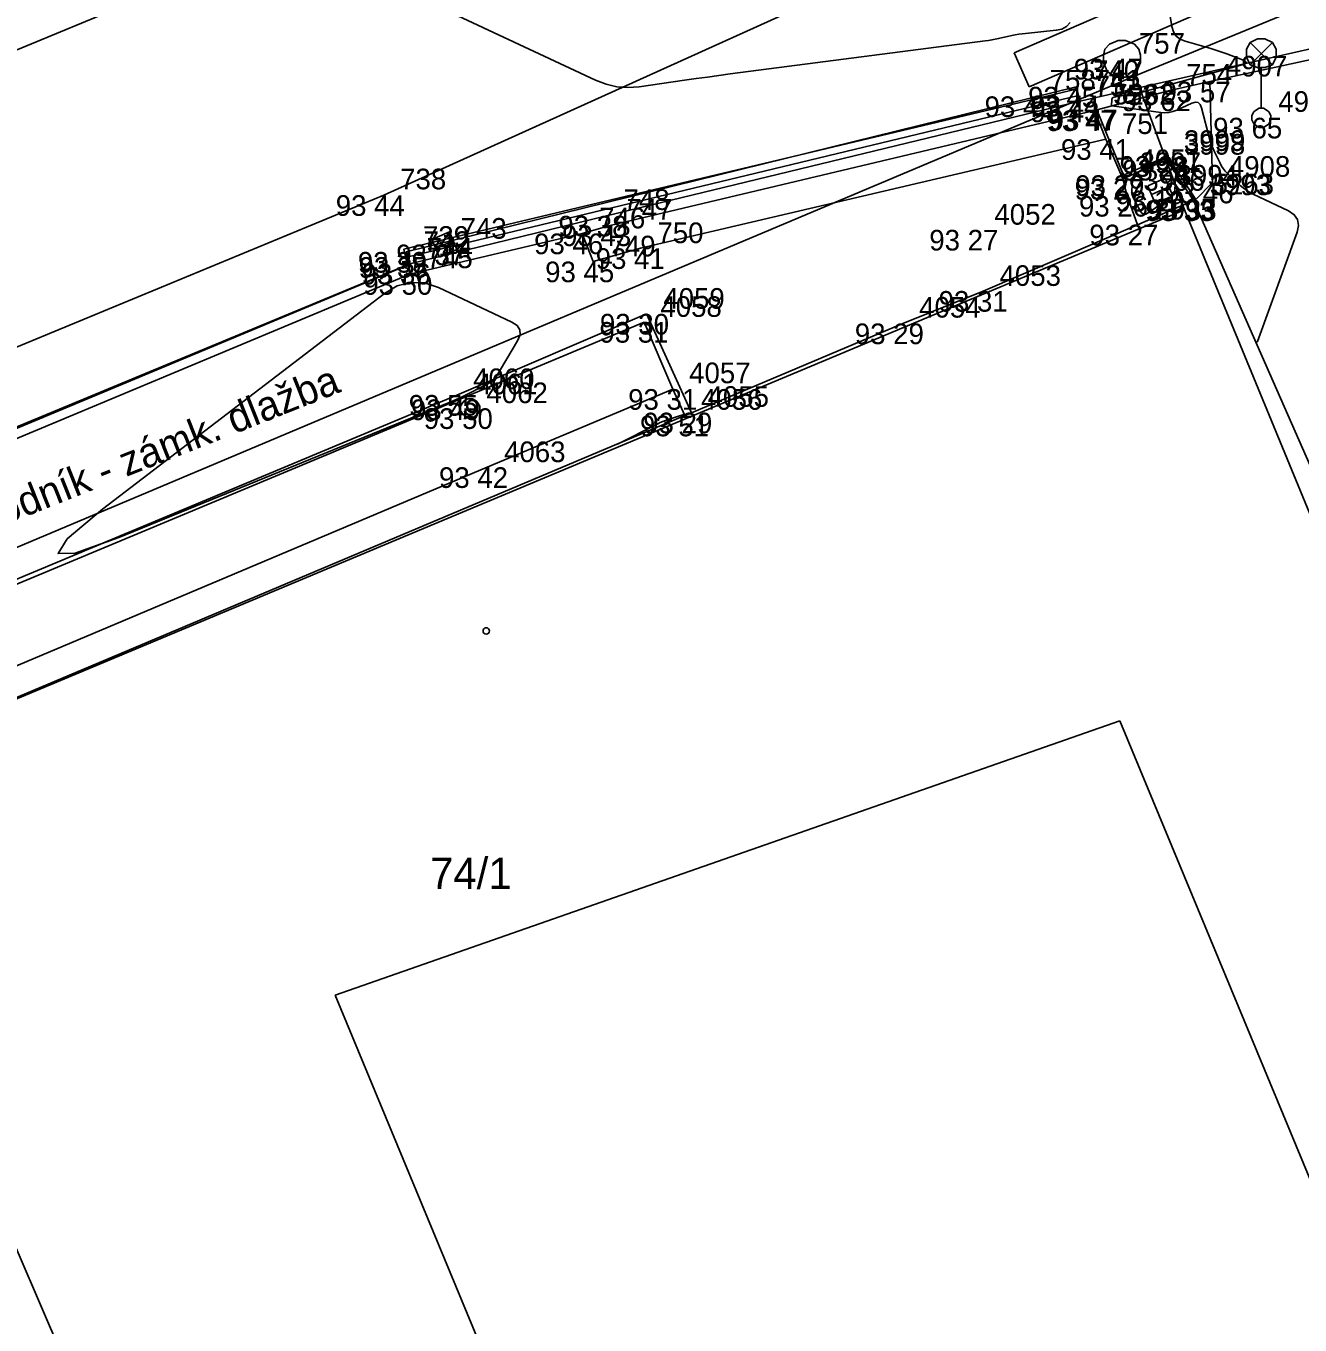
# Model space of a CAD drawing. Extents: x -711081 to -709338, y -1025122 to -1024092.
# Drawn here: x -709841.94 to -709824.66, y -1024568.73 to -1024551.11 of the extents above; entities that cross this region are included whole.
import ezdxf

# ---------------------------------------------------------------- set-up
doc = ezdxf.new("R2010")
doc.units = 0
for name, color, linetype in [('Ex_Minor Contours', 7, 'Continuous'), ('Z_body', 7, 'Continuous'), ('Z_body_cisla', 7, 'Continuous'), ('Z_body_vysky_redukovane', 7, 'Continuous'), ('Z_budova', 7, 'Continuous'), ('Z_chodnik', 7, 'Continuous'), ('Z_hrany_paty', 7, 'Continuous'), ('Z_katastr_cisla_stavebni', 7, 'Continuous'), ('Z_katastr_hranice', 7, 'Continuous'), ('Z_katastr_vnitrni_kresba', 7, 'Continuous'), ('Z_katastr_znacky_budov', 7, 'Continuous'), ('Z_komunikace', 7, 'Continuous'), ('Z_komunikace_osa', 7, 'Continuous'), ('Z_obruba', 7, 'Continuous'), ('Z_popisy', 7, 'Continuous'), ('Z_rozhranni', 7, 'Continuous'), ('Z_site_kanalizace_znaky', 7, 'Continuous'), ('Z_site_vo_znaky', 7, 'Continuous'), ('Z_site_vodovod_znaky', 7, 'Continuous'), ('Z_vdz25_plna', 7, 'Continuous'), ('Z_vdz_prechod', 7, 'Continuous'), ('Z_vstupy', 7, 'Continuous'), ('Z_zlabek', 7, 'Continuous')]:
    doc.layers.add(name, color=color, linetype=linetype)

# ---------------------------------------------------------------- blocks, each defined once
blk = doc.blocks.new('POINT_DISPLAY')
blk.add_line((0, 0), (0, 0))
blk = doc.blocks.new('Z614')
for p, q in [((-0.13, 0.03), (-0.1, 0.08)), ((-0.13, -0.03), (-0.13, 0.03)), ((-0.1, 0.08), (-0.08, 0.1)), ((-0.08, 0.1), (-0.03, 0.13)), ((-0.03, 0.13), (0.03, 0.13)), ((0.03, 0.13), (0.08, 0.1)), ((0.08, 0.1), (0.1, 0.08)), ((0.1, 0.08), (0.13, 0.03)), ((0.13, 0.03), (0.13, -0.03)), ((-0.1, -0.08), (-0.13, -0.03)), ((-0.08, -0.1), (-0.1, -0.08)), ((-0.03, -0.13), (-0.08, -0.1)), ((0.03, -0.13), (-0.03, -0.13)), ((0.08, -0.1), (0.03, -0.13)), ((0.1, -0.08), (0.08, -0.1)), ((0.13, -0.03), (0.1, -0.08))]:
    blk.add_line(p, q)
blk = doc.blocks.new('Z34')
for p, q in [((-0.15, 1.02), (-0.05, 1.07)), ((-0.05, 1.07), (0.05, 1.07)), ((0.05, 1.07), (0.15, 1.02)), ((-0.2, 0.93), (-0.15, 1.02)), ((-0.2, 0.82), (-0.2, 0.93)), ((0.15, 0.72), (-0.15, 1.02)), ((0.15, 1.02), (-0.15, 0.72)), ((0.15, 1.02), (0.2, 0.93)), ((0.2, 0.93), (0.2, 0.82)), ((-0.15, 0.72), (-0.2, 0.82)), ((-0.05, 0.68), (-0.15, 0.72)), ((0.15, 0.72), (0.05, 0.68)), ((0.2, 0.82), (0.15, 0.72)), ((0.05, 0.68), (-0.05, 0.68)), ((0, 0.13), (0, 0.68)), ((-0.13, 0.03), (-0.1, 0.08)), ((-0.13, -0.03), (-0.13, 0.03)), ((-0.1, 0.08), (-0.08, 0.1)), ((-0.08, 0.1), (-0.03, 0.13)), ((-0.03, 0.13), (0.03, 0.13)), ((0.03, 0.13), (0.08, 0.1)), ((0.08, 0.1), (0.1, 0.08)), ((0.1, 0.08), (0.13, 0.03)), ((0.13, 0.03), (0.13, -0.03)), ((-0.1, -0.08), (-0.13, -0.03)), ((-0.08, -0.1), (-0.1, -0.08)), ((-0.03, -0.13), (-0.08, -0.1)), ((0.03, -0.13), (-0.03, -0.13)), ((0.08, -0.1), (0.03, -0.13)), ((0.1, -0.08), (0.08, -0.1)), ((0.13, -0.03), (0.1, -0.08))]:
    blk.add_line(p, q)
blk = doc.blocks.new('Z620')
for p, q in [((-0.23, 0.13), (-0.17, 0.2)), ((-0.17, 0.2), (-0.05, 0.25)), ((-0.05, 0.25), (0.05, 0.25)), ((0.05, 0.25), (0.17, 0.2)), ((0.17, 0.2), (0.23, 0.13)), ((-0.25, 0.05), (-0.23, 0.13)), ((-0.25, -0.05), (-0.25, 0.05)), ((0.23, 0.13), (0.25, 0.05)), ((0.25, 0.05), (0.25, -0.05)), ((-0.2, -0.17), (-0.25, -0.05)), ((-0.13, -0.23), (-0.2, -0.17)), ((0.2, -0.17), (0.13, -0.23)), ((0.25, -0.05), (0.2, -0.17)), ((-0.05, -0.25), (-0.13, -0.23)), ((0.05, -0.25), (-0.05, -0.25)), ((0.13, -0.23), (0.05, -0.25))]:
    blk.add_line(p, q)
blk = doc.blocks.new('Z46260')
for p, q in [((0.13, 0.13), (-0.13, 0.13)), ((-0.13, 0.13), (-0.13, -0.13)), ((0.13, 0), (-0.13, 0)), ((0.13, -0.13), (0.13, 0.13)), ((-0.13, -0.13), (0.13, -0.13))]:
    blk.add_line(p, q)

msp = doc.modelspace()

# ---------------------------------------------------------------- linework, layer by layer
at = {"layer": 'Ex_Minor Contours'}
for points in [[(-709826.732, -1024549.131), (-709826.402, -1024551.122), (-709826.381, -1024551.194), (-709826.345, -1024551.251), (-709826.292, -1024551.294), (-709826.223, -1024551.323), (-709825.873, -1024551.422), (-709825.819, -1024551.438), (-709825.765, -1024551.455), (-709825.712, -1024551.473), (-709825.658, -1024551.493), (-709825.447, -1024551.572), (-709825.407, -1024551.591), (-709825.395, -1024551.609), (-709825.409, -1024551.626), (-709825.45, -1024551.642), (-709826.674, -1024551.976), (-709826.727, -1024551.99), (-709826.781, -1024552.003), (-709826.834, -1024552.014), (-709826.888, -1024552.025), (-709827.185, -1024552.08), (-709827.198, -1024552.084), (-709827.207, -1024552.091), (-709827.213, -1024552.1), (-709827.215, -1024552.113), (-709827.222, -1024552.197), (-709827.219, -1024552.199), (-709826.553, -1024552.289), (-709826.498, -1024552.293), (-709826.443, -1024552.288), (-709826.39, -1024552.276), (-709826.337, -1024552.257), (-709826.131, -1024552.161), (-709826.084, -1024552.147), (-709826.046, -1024552.153), (-709826.018, -1024552.179), (-709825.999, -1024552.224), (-709825.886, -1024552.657), (-709825.874, -1024552.699), (-709825.86, -1024552.74), (-709825.844, -1024552.781), (-709825.826, -1024552.82), (-709825.749, -1024552.977), (-709825.729, -1024553.014), (-709825.705, -1024553.05), (-709825.678, -1024553.083), (-709825.648, -1024553.114), (-709825.475, -1024553.277), (-709825.434, -1024553.312), (-709825.391, -1024553.344), (-709825.346, -1024553.372), (-709825.298, -1024553.397), (-709824.822, -1024553.623), (-709824.743, -1024553.675), (-709824.697, -1024553.74), (-709824.684, -1024553.82), (-709824.703, -1024553.912), (-709825.242, -1024555.394), (-709825.243, -1024555.396), (-709825.245, -1024555.398), (-709825.247, -1024555.4), (-709825.249, -1024555.401), (-709825.263, -1024555.406)], [(-709836.368, -1024550.848), (-709834.218, -1024551.851), (-709834.075, -1024551.906), (-709833.929, -1024551.939), (-709833.78, -1024551.95), (-709833.627, -1024551.939), (-709833.011, -1024551.85), (-709832.857, -1024551.829), (-709832.702, -1024551.807), (-709832.548, -1024551.786), (-709832.394, -1024551.766), (-709828.936, -1024551.317), (-709828.89, -1024551.31), (-709828.844, -1024551.303), (-709828.799, -1024551.294), (-709828.753, -1024551.285), (-709828.572, -1024551.245), (-709828.526, -1024551.235), (-709828.48, -1024551.227), (-709828.434, -1024551.221), (-709828.388, -1024551.215), (-709827.972, -1024551.173), (-709827.895, -1024551.156), (-709827.831, -1024551.12), (-709827.782, -1024551.067)], [(-709833.924, -1024556.785), (-709833.376, -1024556.512), (-709833.342, -1024556.495), (-709833.307, -1024556.48), (-709833.271, -1024556.466), (-709833.235, -1024556.454), (-709833.023, -1024556.384), (-709833.021, -1024556.383), (-709833.018, -1024556.383), (-709833.017, -1024556.384), (-709833.015, -1024556.386), (-709833.006, -1024556.398)]]:
    msp.add_lwpolyline(points, dxfattribs=at)
for points in [[(-709826.932, -1024553.214), (-709826.938, -1024553.231), (-709826.942, -1024553.249), (-709826.943, -1024553.266), (-709826.945, -1024553.365), (-709826.944, -1024553.387), (-709826.94, -1024553.409), (-709826.934, -1024553.429), (-709826.924, -1024553.45), (-709826.831, -1024553.624), (-709826.81, -1024553.652), (-709826.785, -1024553.666), (-709826.757, -1024553.665), (-709826.726, -1024553.65), (-709826.428, -1024553.447), (-709826.401, -1024553.424), (-709826.381, -1024553.398), (-709826.369, -1024553.367), (-709826.363, -1024553.333), (-709826.35, -1024553.116), (-709826.349, -1024553.114), (-709826.348, -1024553.113), (-709826.341, -1024553.11), (-709826.341, -1024553.109), (-709826.341, -1024553.108), (-709826.433, -1024552.954), (-709826.45, -1024552.932), (-709826.47, -1024552.921), (-709826.494, -1024552.919), (-709826.52, -1024552.926), (-709826.736, -1024553.022), (-709826.751, -1024553.029), (-709826.764, -1024553.036), (-709826.778, -1024553.044), (-709826.791, -1024553.052), (-709826.844, -1024553.086), (-709826.856, -1024553.095), (-709826.867, -1024553.106), (-709826.877, -1024553.118), (-709826.886, -1024553.131), (-709826.924, -1024553.198)], [(-709835.283, -1024555.178), (-709835.246, -1024555.237), (-709835.244, -1024555.306), (-709835.278, -1024555.386), (-709835.583, -1024555.896), (-709835.584, -1024555.898), (-709835.584, -1024555.9), (-709835.584, -1024555.902), (-709835.582, -1024555.903), (-709835.575, -1024555.91), (-709835.573, -1024555.912), (-709835.573, -1024555.913), (-709835.574, -1024555.915), (-709835.575, -1024555.916), (-709835.949, -1024556.106), (-709836.012, -1024556.137), (-709836.076, -1024556.167), (-709836.141, -1024556.196), (-709836.206, -1024556.223), (-709840.686, -1024558.052), (-709841.276, -1024558.263), (-709841.509, -1024558.27), (-709841.385, -1024558.072), (-709840.905, -1024557.67), (-709837.083, -1024554.743), (-709836.909, -1024554.639), (-709836.728, -1024554.592), (-709836.541, -1024554.6), (-709836.349, -1024554.664), (-709835.356, -1024555.13)]]:
    msp.add_lwpolyline(points, close=True, dxfattribs=at)
at = {"layer": 'Z_budova'}
for p, q in [((-709826.11, -1024553.48), (-709826.87, -1024553.81)), ((-709826.11, -1024553.48), (-709823.67, -1024559.03)), ((-709828.96, -1024554.71), (-709830.05, -1024555.15)), ((-709833.01, -1024556.4), (-709844.89, -1024561.41)), ((-709832.92, -1024556.36), (-709833.01, -1024556.4))]:
    msp.add_line(p, q, dxfattribs=at)
at = {"layer": 'Z_chodnik'}
for p, q in [((-709827.45, -1024552.26), (-709827.3, -1024552.65)), ((-709827.3, -1024552.65), (-709827.07, -1024553.19)), ((-709827.01, -1024553.42), (-709827.07, -1024553.19)), ((-709827.01, -1024553.42), (-709826.87, -1024553.81)), ((-709833.53, -1024555.02), (-709836.1, -1024556.12)), ((-709833.53, -1024555.02), (-709832.92, -1024556.36)), ((-709836.1, -1024556.12), (-709849.57, -1024561.75))]:
    msp.add_line(p, q, dxfattribs=at)
at = {"layer": 'Z_hrany_paty'}
for p in [(-709825.89, -1024551.87), (-709826.08, -1024553.47)]:
    msp.add_line(p, (-709825.85, -1024553.24), dxfattribs=at)
at = {"layer": 'Z_katastr_hranice'}
for p, q in [((-709808.2, -1024544.08), (-709826.9, -1024551.79)), ((-709826.9, -1024551.79), (-709827.66, -1024552.11)), ((-709826.23, -1024553.61), (-709826.9, -1024551.79)), ((-709827.66, -1024552.11), (-709845.54, -1024559.65)), ((-709836.82, -1024554.14), (-709827.7, -1024551.97)), ((-709827.7, -1024551.97), (-709827.66, -1024552.11)), ((-709823.95, -1024559.15), (-709826.23, -1024553.61)), ((-709836.77, -1024554.36), (-709836.82, -1024554.14)), ((-709850.71, -1024560.17), (-709836.77, -1024554.36)), ((-709844.8, -1024561.38), (-709839.9, -1024572.74))]:
    msp.add_line(p, q, dxfattribs=at)
at = {"layer": 'Z_katastr_vnitrni_kresba'}
for p, q in [((-709826.23, -1024553.61), (-709844.8, -1024561.38)), ((-709837.75, -1024564.26), (-709827.11, -1024560.54)), ((-709822.5, -1024571.65), (-709827.11, -1024560.54)), ((-709835.08, -1024570.7), (-709837.75, -1024564.26))]:
    msp.add_line(p, q, dxfattribs=at)
at = {"layer": 'Z_katastr_znacky_budov'}
msp.add_circle((-709835.702, -1024559.32), 0.0437, dxfattribs=at)
at = {"layer": 'Z_komunikace'}
for p, q in [((-709827.67, -1024552.14), (-709824.01, -1024551.31)), ((-709834.07, -1024553.69), (-709827.67, -1024552.14)), ((-709836.74, -1024554.34), (-709834.07, -1024553.69)), ((-709851.14, -1024560.31), (-709836.74, -1024554.34))]:
    msp.add_line(p, q, dxfattribs=at)
at = {"layer": 'Z_komunikace_osa'}
msp.add_line((-709852.88, -1024555.91), (-709836.73, -1024549.23), dxfattribs=at)
at = {"layer": 'Z_obruba'}
for p, q in [((-709825.89, -1024551.87), (-709823.93, -1024551.44)), ((-709826.43, -1024551.99), (-709825.89, -1024551.87)), ((-709827.45, -1024552.26), (-709826.43, -1024551.99)), ((-709834.02, -1024553.82), (-709827.45, -1024552.26)), ((-709827.06, -1024553.14), (-709827.42, -1024552.25)), ((-709826.46, -1024552.88), (-709827.06, -1024553.14)), ((-709826.46, -1024552.88), (-709826.08, -1024553.47)), ((-709826.11, -1024553.48), (-709826.08, -1024553.47)), ((-709834.4, -1024553.93), (-709834.02, -1024553.82)), ((-709836.74, -1024554.48), (-709834.4, -1024553.93)), ((-709851.1, -1024560.48), (-709836.74, -1024554.48)), ((-709833.56, -1024555.13), (-709836.07, -1024556.18)), ((-709833.17, -1024556.04), (-709833.56, -1024555.13)), ((-709833.17, -1024556.04), (-709833.01, -1024556.4)), ((-709836.07, -1024556.18), (-709849.57, -1024561.82))]:
    msp.add_line(p, q, dxfattribs=at)
at = {"layer": 'Z_rozhranni'}
for p, q in [((-709836.79, -1024554.18), (-709827.7, -1024551.94)), ((-709827.7, -1024551.94), (-709827.67, -1024552.06)), ((-709827.67, -1024552.06), (-709827.67, -1024552.14)), ((-709833.61, -1024554.13), (-709827.3, -1024552.65)), ((-709827.07, -1024553.19), (-709826.47, -1024552.93)), ((-709826.47, -1024552.93), (-709826.11, -1024553.48)), ((-709834.25, -1024554.31), (-709834.4, -1024553.93)), ((-709836.79, -1024554.18), (-709836.78, -1024554.25)), ((-709834.25, -1024554.31), (-709833.61, -1024554.13)), ((-709836.78, -1024554.25), (-709836.74, -1024554.34)), ((-709835.69, -1024557.1), (-709833.17, -1024556.04)), ((-709835.69, -1024557.1), (-709845.01, -1024561.03))]:
    msp.add_line(p, q, dxfattribs=at)
at = {"layer": 'Z_vdz25_plna'}
for p, q in [((-709837.09, -1024553.41), (-709829.73, -1024550.08)), ((-709851.52, -1024559.37), (-709837.09, -1024553.41))]:
    msp.add_line(p, q, dxfattribs=at)
at = {"layer": 'Z_vdz_prechod'}
for p, q in [((-709824.79, -1024549.85), (-709828.54, -1024551.48)), ((-709828.34, -1024551.94), (-709824.59, -1024550.31)), ((-709828.54, -1024551.48), (-709828.34, -1024551.94))]:
    msp.add_line(p, q, dxfattribs=at)
at = {"layer": 'Z_vstupy'}
for p, q in [((-709828.96, -1024554.71), (-709826.87, -1024553.81)), ((-709832.92, -1024556.36), (-709830.05, -1024555.15))]:
    msp.add_line(p, q, dxfattribs=at)
at = {"layer": 'Z_zlabek'}
msp.add_line((-709827.67, -1024552.06), (-709836.78, -1024554.25), dxfattribs=at)

# ---------------------------------------------------------------- block references
at = {"layer": 'Z_body'}
for p in [(-709827.08, -1024551.56), (-709827.7, -1024551.94), (-709825.89, -1024551.87), (-709828.29, -1024552.07), (-709827.67, -1024552.06), (-709826.43, -1024551.99), (-709827.67, -1024552.14), (-709827.45, -1024552.26), (-709827.42, -1024552.25), (-709825.19, -1024552.36), (-709827.3, -1024552.65), (-709826.47, -1024552.93), (-709826.46, -1024552.88), (-709827.06, -1024553.14), (-709827.07, -1024553.19), (-709826.56, -1024553.35), (-709825.85, -1024553.24), (-709837.09, -1024553.41), (-709827.01, -1024553.42), (-709826.11, -1024553.48), (-709826.08, -1024553.47), (-709834.07, -1024553.69), (-709834.02, -1024553.82), (-709829.04, -1024553.88), (-709826.87, -1024553.81), (-709834.4, -1024553.93), (-709836.79, -1024554.18), (-709836.27, -1024554.08), (-709833.61, -1024554.13), (-709836.78, -1024554.25), (-709836.74, -1024554.34), (-709834.25, -1024554.31), (-709836.74, -1024554.48), (-709828.96, -1024554.71), (-709833.53, -1024555.02), (-709833.56, -1024555.13), (-709830.05, -1024555.15), (-709836.1, -1024556.12), (-709833.17, -1024556.04), (-709836.07, -1024556.18), (-709835.92, -1024556.3), (-709833.01, -1024556.4), (-709832.92, -1024556.36), (-709835.69, -1024557.1)]:
    msp.add_blockref('POINT_DISPLAY', p, dxfattribs=at)
at = {"layer": 'Z_site_kanalizace_znaky'}
msp.add_blockref('Z620', (-709827.08, -1024551.56), dxfattribs=at)
at = {"layer": 'Z_site_kanalizace_znaky', "rotation": 23.399999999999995}
for p in [(-709826.56, -1024553.35), (-709836.27, -1024554.08)]:
    msp.add_blockref('Z46260', p, dxfattribs=at)
at = {"layer": 'Z_site_vo_znaky'}
msp.add_blockref('Z34', (-709825.19, -1024552.36), dxfattribs=at)
at = {"layer": 'Z_site_vodovod_znaky'}
msp.add_blockref('Z614', (-709835.92, -1024556.3), dxfattribs=at)

# ---------------------------------------------------------------- texts
at = {"layer": 'Z_body_cisla'}
for s, p in [('757', (-709826.85, -1024551.49)), ('740', (-709827.47, -1024551.86)), ('4907', (-709825.67, -1024551.8)), ('758', (-709828.06, -1024551.99)), ('741', (-709827.45, -1024551.99)), ('754', (-709826.21, -1024551.91)), ('752', (-709827.45, -1024552.07)), ('753', (-709827.22, -1024552.19)), ('5262', (-709827.2, -1024552.18)), ('4906', (-709824.96, -1024552.28)), ('751', (-709827.08, -1024552.58)), ('3999', (-709826.24, -1024552.81)), ('3998', (-709826.24, -1024552.86)), ('4051', (-709826.84, -1024553.07)), ('3997', (-709826.84, -1024553.11)), ('3994', (-709826.34, -1024553.28)), ('4908', (-709825.63, -1024553.16)), ('738', (-709836.87, -1024553.33)), ('3996', (-709826.79, -1024553.35)), ('3993', (-709825.89, -1024553.41)), ('5263', (-709825.85, -1024553.4)), ('748', (-709833.84, -1024553.61)), ('747', (-709833.8, -1024553.74)), ('4052', (-709828.81, -1024553.81)), ('3995', (-709826.64, -1024553.74)), ('746', (-709834.17, -1024553.86)), ('739', (-709836.56, -1024554.11)), ('743', (-709836.05, -1024554)), ('750', (-709833.38, -1024554.06)), ('742', (-709836.55, -1024554.18)), ('744', (-709836.51, -1024554.27)), ('749', (-709834.03, -1024554.24)), ('745', (-709836.51, -1024554.4)), ('4053', (-709828.74, -1024554.64)), ('4059', (-709833.3, -1024554.95)), ('4058', (-709833.34, -1024555.06)), ('4054', (-709829.83, -1024555.07)), ('4060', (-709835.88, -1024556.04)), ('4057', (-709832.95, -1024555.96)), ('4061', (-709835.84, -1024556.11)), ('4062', (-709835.7, -1024556.23)), ('4055', (-709832.7, -1024556.28)), ('4056', (-709832.79, -1024556.32)), ('4063', (-709835.46, -1024557.03))]:
    msp.add_text(s, height=0.28, dxfattribs=at).set_placement(p)
at = {"layer": 'Z_body_vysky_redukovane'}
for s, p in [('93 47', (-709827.733, -1024551.84)), ('93 45', (-709828.353, -1024552.22)), ('93 57', (-709826.543, -1024552.15)), ('93 45', (-709828.943, -1024552.35)), ('93 44', (-709828.323, -1024552.34)), ('93 62', (-709827.083, -1024552.27)), ('93 43', (-709828.323, -1024552.42)), ('93 47', (-709828.103, -1024552.54)), ('93 47', (-709828.073, -1024552.53)), ('93 65', (-709825.843, -1024552.64)), ('93 41', (-709827.907, -1024552.93)), ('93 28', (-709827.113, -1024553.16)), ('93 21', (-709827.077, -1024553.21)), ('93 29', (-709827.713, -1024553.42)), ('93 27', (-709827.723, -1024553.47)), ('93 19', (-709827.167, -1024553.63)), ('93 46', (-709826.503, -1024553.52)), ('93 44', (-709837.743, -1024553.69)), ('93 26', (-709827.663, -1024553.7)), ('93 33', (-709826.763, -1024553.76)), ('93 33', (-709826.733, -1024553.75)), ('93 38', (-709834.723, -1024553.97)), ('93 43', (-709834.673, -1024554.1)), ('93 27', (-709829.693, -1024554.16)), ('93 27', (-709827.523, -1024554.09)), ('93 46', (-709835.053, -1024554.21)), ('93 39', (-709837.443, -1024554.46)), ('93 37', (-709836.923, -1024554.36)), ('93 41', (-709834.217, -1024554.41)), ('93 35', (-709837.433, -1024554.53)), ('93 36', (-709837.393, -1024554.62)), ('93 45', (-709834.903, -1024554.59)), ('93 50', (-709837.37, -1024554.76)), ('93 31', (-709829.567, -1024554.99)), ('93 30', (-709834.16, -1024555.3)), ('93 31', (-709834.167, -1024555.41)), ('93 29', (-709830.703, -1024555.43)), ('93 55', (-709836.753, -1024556.4)), ('93 49', (-709836.723, -1024556.46)), ('93 31', (-709833.777, -1024556.32)), ('93 50', (-709836.55, -1024556.58)), ('93 51', (-709833.617, -1024556.68)), ('93 29', (-709833.573, -1024556.64)), ('93 42', (-709836.343, -1024557.38))]:
    msp.add_text(s, height=0.28, dxfattribs=at).set_placement(p)
at = {"layer": 'Z_katastr_cisla_stavebni'}
msp.add_text('74/1', height=0.425, dxfattribs=at).set_placement((-709836.464, -1024562.82))
at = {"layer": 'Z_popisy'}
msp.add_text('Chodník - zámk. dlažba', height=0.4, rotation=21.6, dxfattribs=at).set_placement((-709842.88, -1024558.14))

doc.saveas('drawing.dxf')
